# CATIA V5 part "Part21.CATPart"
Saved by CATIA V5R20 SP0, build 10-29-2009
Part number: socket countersunk head screw_din_DIN 7991 - M6 x 16 --- 16N
Revision: ANY
Definition: UNKNOWN
Nomenclature: socket countersunk head screw_din_DIN 7991 - M6 x 16 --- 16N
Source: Unknown
Bounding box of the stored display mesh (mm): x 0 to 16, y -5.785 to 5.785, z -5.785 to 5.785
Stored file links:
  C:\Users\Utente\Desktop\IO LAVORO\3D X SITO CF\CUMSA\3D files GR\GR 283432-15\Part21.CATPart
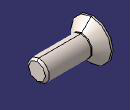
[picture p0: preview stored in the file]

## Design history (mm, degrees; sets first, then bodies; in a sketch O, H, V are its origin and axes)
Body1 "Hex" (main body)
  Solid1: solid without history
